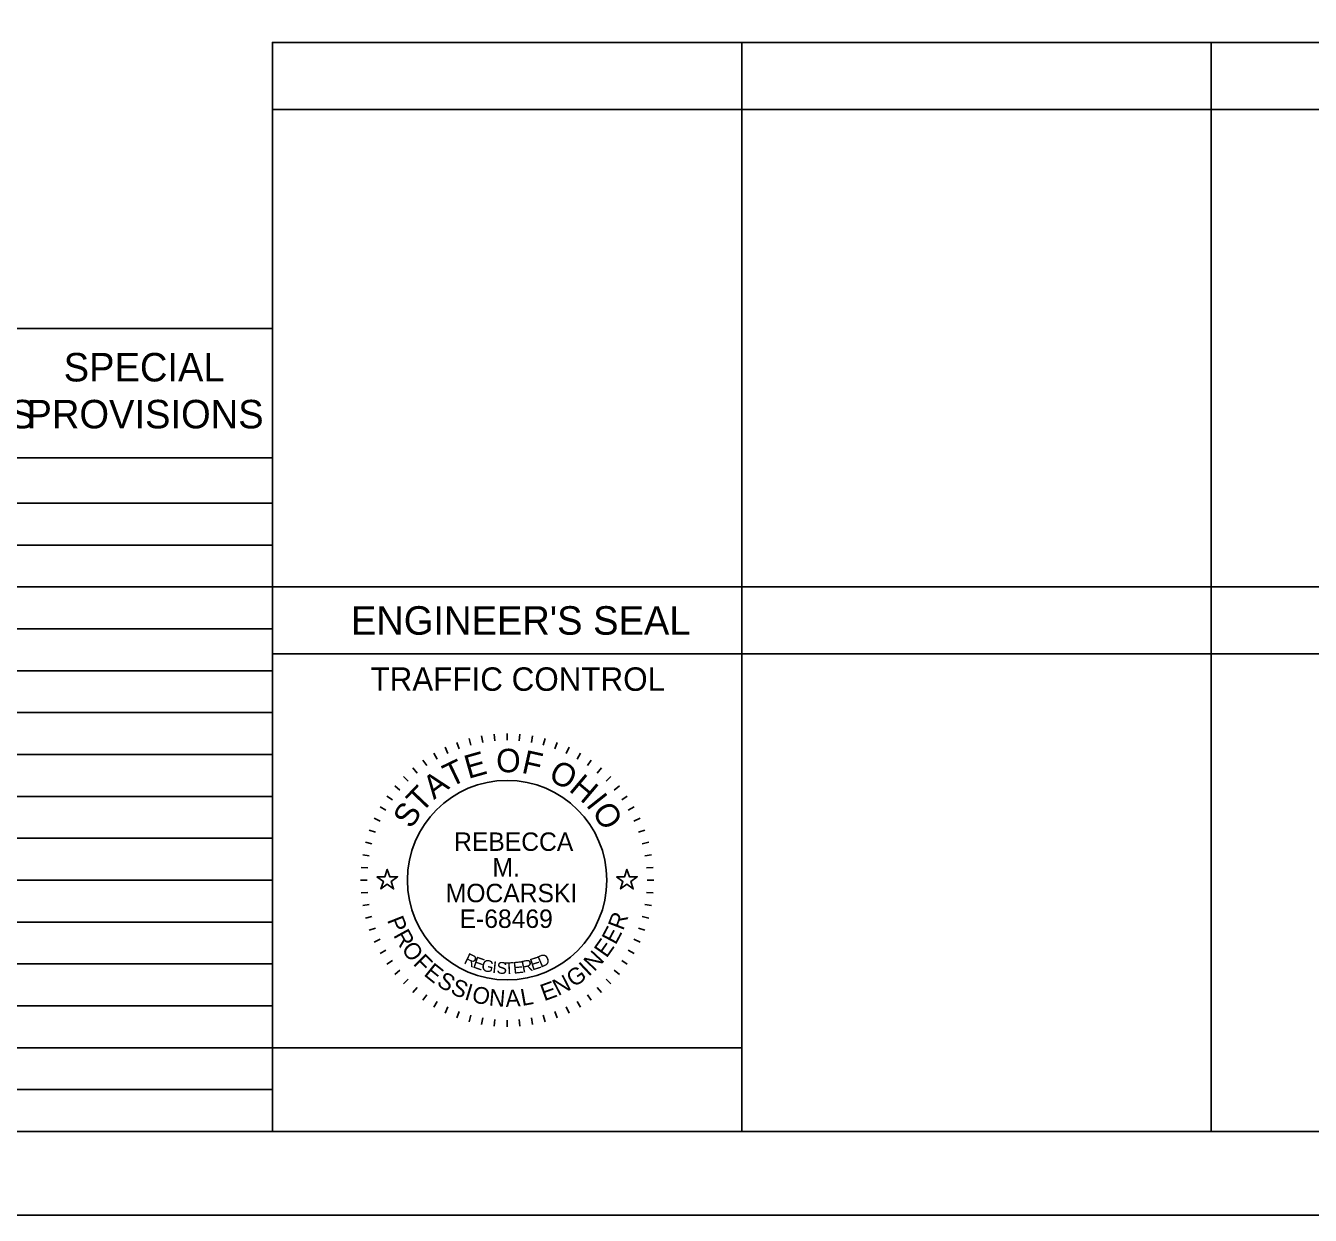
# Model space of a CAD drawing. Extents: x 0 to 29006, y 0 to 889393.
# Drawn here: x 22.13 to 29.79, y 0 to 7.1 of the extents above; entities that cross this region are included whole.
import ezdxf

# ---------------------------------------------------------------- set-up
doc = ezdxf.new("R2010")
doc.units = 0
for name, color, linetype in [('GM_X_Corporation', 7, 'Continuous'), ('SH_Border', 7, 'Continuous'), ('SH_Cut_Line', 7, 'Continuous'), ('SH_Data', 7, 'Continuous'), ('SH_Text', 7, 'Continuous')]:
    doc.layers.add(name, color=color, linetype=linetype)

msp = doc.modelspace()

# ---------------------------------------------------------------- linework, layer by layer
at = {"layer": 'GM_X_Corporation'}
for p, q in [((24.7735, 2.8452), (24.7839, 2.8065)), ((24.8481, 2.8617), (24.855, 2.8223)), ((24.9237, 2.8717), (24.9272, 2.8318)), ((25, 2.875), (25, 2.835)), ((25.0763, 2.8717), (25.0728, 2.8318)), ((25.1519, 2.8617), (25.145, 2.8223)), ((25.2265, 2.8452), (25.2161, 2.8065)), ((24.6302, 2.793), (24.6471, 2.7568)), ((24.7007, 2.8222), (24.7144, 2.7846)), ((25.2993, 2.8222), (25.2856, 2.7846)), ((25.3698, 2.793), (25.3529, 2.7568)), ((24.4981, 2.7168), (24.5211, 2.684)), ((24.5625, 2.7578), (24.5825, 2.7231)), ((25.4375, 2.7578), (25.4175, 2.7231)), ((25.5019, 2.7168), (25.4789, 2.684)), ((24.3813, 2.6187), (24.4096, 2.5904)), ((24.4376, 2.6703), (24.4633, 2.6396)), ((25.5624, 2.6703), (25.5367, 2.6396)), ((25.6187, 2.6187), (25.5904, 2.5904)), ((24.3297, 2.5624), (24.3604, 2.5367)), ((25.6703, 2.5624), (25.6396, 2.5367)), ((24.2832, 2.5019), (24.316, 2.4789)), ((25.7168, 2.5019), (25.684, 2.4789)), ((24.2422, 2.4375), (24.2769, 2.4175)), ((25.7578, 2.4375), (25.7231, 2.4175)), ((24.207, 2.3698), (24.2432, 2.3529)), ((25.793, 2.3698), (25.7568, 2.3529)), ((24.1548, 2.2265), (24.1935, 2.2161)), ((24.1778, 2.2993), (24.2154, 2.2856)), ((25.8222, 2.2993), (25.7846, 2.2856)), ((25.8452, 2.2265), (25.8065, 2.2161)), ((24.1383, 2.1519), (24.1777, 2.145)), ((25.8617, 2.1519), (25.8223, 2.145)), ((24.1283, 2.0763), (24.1682, 2.0728)), ((25.8717, 2.0763), (25.8318, 2.0728)), ((24.125, 2), (24.165, 2)), ((25.875, 2), (25.835, 2)), ((24.1283, 1.9237), (24.1682, 1.9272)), ((25.8717, 1.9237), (25.8318, 1.9272)), ((24.1383, 1.8481), (24.1777, 1.855)), ((25.8617, 1.8481), (25.8223, 1.855)), ((24.1548, 1.7735), (24.1935, 1.7839)), ((25.8452, 1.7735), (25.8065, 1.7839)), ((24.1778, 1.7007), (24.2154, 1.7144)), ((25.8222, 1.7007), (25.7846, 1.7144)), ((24.207, 1.6302), (24.2432, 1.6471)), ((25.793, 1.6302), (25.7568, 1.6471)), ((24.2422, 1.5625), (24.2769, 1.5825)), ((25.7578, 1.5625), (25.7231, 1.5825)), ((24.2832, 1.4981), (24.316, 1.5211)), ((24.3297, 1.4376), (24.3604, 1.4633)), ((25.6703, 1.4376), (25.6396, 1.4633)), ((25.7168, 1.4981), (25.684, 1.5211)), ((24.3813, 1.3813), (24.4096, 1.4096)), ((25.6187, 1.3813), (25.5904, 1.4096)), ((24.4376, 1.3297), (24.4633, 1.3604)), ((24.4981, 1.2832), (24.5211, 1.316)), ((25.5019, 1.2832), (25.4789, 1.316)), ((25.5624, 1.3297), (25.5367, 1.3604)), ((24.5625, 1.2422), (24.5825, 1.2769)), ((24.6302, 1.207), (24.6471, 1.2432)), ((25.3698, 1.207), (25.3529, 1.2432)), ((25.4375, 1.2422), (25.4175, 1.2769)), ((24.7007, 1.1778), (24.7144, 1.2154)), ((24.7735, 1.1548), (24.7839, 1.1935)), ((24.8481, 1.1383), (24.855, 1.1777)), ((24.9237, 1.1283), (24.9272, 1.1682)), ((25, 1.125), (25, 1.165)), ((25.0763, 1.1283), (25.0728, 1.1682)), ((25.1519, 1.1383), (25.145, 1.1777)), ((25.2265, 1.1548), (25.2161, 1.1935)), ((25.2993, 1.1778), (25.2856, 1.2154))]:
    msp.add_line(p, q, dxfattribs=at)
for points in [[(24.2236, 2.02), (24.2705, 2.02), (24.285, 2.0645), (24.2995, 2.02), (24.3464, 2.02), (24.3085, 1.9924), (24.323, 1.9478), (24.285, 1.9754), (24.247, 1.9478), (24.2615, 1.9924)], [(25.6536, 2.02), (25.7005, 2.02), (25.715, 2.0645), (25.7295, 2.02), (25.7764, 2.02), (25.7385, 1.9924), (25.753, 1.9478), (25.715, 1.9754), (25.677, 1.9478), (25.6915, 1.9924)]]:
    msp.add_lwpolyline(points, close=True, dxfattribs=at)
msp.add_circle((25, 2), 0.595, dxfattribs=at)
at = {"layer": 'SH_Border'}
msp.add_lwpolyline([(1.5, 21.5), (33.5, 21.5), (33.5, 0.5), (1.5, 0.5)], close=True, dxfattribs=at)
at = {"layer": 'SH_Cut_Line'}
msp.add_lwpolyline([(0, 0), (34, 0), (34, 22), (0, 22)], close=True, dxfattribs=at)
at = {"layer": 'SH_Data'}
for p, q in [((23.6, 6.6), (26.4, 6.6)), ((26.4, 6.6), (29.2, 6.6)), ((29.2, 6.6), (32, 6.6)), ((10.15, 5.2917), (23.6, 5.2917)), ((23.6, 0.5), (23.6, 5.2917)), ((10.15, 4.5209), (23.6, 4.5209)), ((10.15, 4.25), (23.6, 4.25)), ((10.15, 4), (23.6, 4)), ((10.15, 3.75), (23.6, 3.75)), ((23.6, 0.5), (23.6, 3.75)), ((23.6, 3.75), (26.4, 3.75)), ((26.4, 3.75), (26.4, 0.5)), ((10.15, 3.5), (23.6, 3.5)), ((23.6, 3.35), (26.4, 3.35)), ((23.6, 3.35), (26.4, 3.35)), ((26.4, 3.35), (29.2, 3.35)), ((29.2, 3.35), (32, 3.35)), ((10.15, 3.25), (23.6, 3.25)), ((10.15, 3), (23.6, 3)), ((10.15, 2.75), (23.6, 2.75)), ((10.15, 2.5), (23.6, 2.5)), ((10.15, 2.25), (23.6, 2.25)), ((10.15, 2), (23.6, 2)), ((10.15, 1.75), (23.6, 1.75)), ((10.15, 1.5), (23.6, 1.5)), ((10.15, 1.25), (23.6, 1.25)), ((10.15, 1), (23.6, 1)), ((10.15, 0.75), (23.6, 0.75)), ((23.6, 0.5), (26.4, 0.5))]:
    msp.add_line(p, q, dxfattribs=at)
for points in [[(26.4, 7), (23.6, 7), (23.6, 3.75), (26.4, 3.75)], [(29.2, 7), (26.4, 7), (26.4, 3.75), (29.2, 3.75)], [(32, 7), (29.2, 7), (29.2, 3.75), (32, 3.75)], [(26.4, 3.75), (23.6, 3.75), (23.6, 0.5), (26.4, 0.5)], [(29.2, 3.75), (26.4, 3.75), (26.4, 0.5), (29.2, 0.5)], [(32, 3.75), (29.2, 3.75), (29.2, 0.5), (32, 0.5)], [(23.6, 0.5), (23.6, 1), (26.4, 1), (26.4, 0.5)]]:
    msp.add_lwpolyline(points, close=True, dxfattribs=at)

# ---------------------------------------------------------------- texts
at = {"layer": 'GM_X_Corporation'}
for s, height, rotation, p in [('E', 0.14, 15.75706, (24.7684, 2.6038)), ('O', 0.14, 359.78119, (24.9347, 2.6443)), ('F', 0.14, 347.43619, (25.0811, 2.6417)), ('T', 0.14, 25.71674, (24.6616, 2.5518)), ('O', 0.14, 332.25863, (25.2398, 2.6015)), ('A', 0.14, 36.47472, (24.5634, 2.4781)), ('H', 0.14, 319.91363, (25.3632, 2.5361)), ('T', 0.14, 46.4344, (24.4883, 2.3964)), ('S', 0.14, 57.19238, (24.4281, 2.3014)), ('I', 0.14, 308.36695, (25.4665, 2.4483)), ('O', 0.14, 303.14906, (25.5021, 2.4089)), ('P', 0.1, 291.49398, (24.2823, 1.7621)), ('R', 0.1, 69.23216, (25.6919, 1.6954)), ('R', 0.1, 298.73106, (24.319, 1.6717)), ('E', 0.1, 61.99508, (25.6476, 1.6098)), ('O', 0.1, 306.46664, (24.3655, 1.5883)), ('E', 0.1, 54.75801, (25.5933, 1.5314)), ('F', 0.1, 314.7068, (24.4343, 1.4983)), ('R', 0.07, 334.48695, (24.7375, 1.5051)), ('E', 0.07, 341.03996, (24.7906, 1.4801)), ('E', 0.07, 17.68363, (25.1498, 1.4602)), ('D', 0.07, 23.30524, (25.201, 1.477)), ('N', 0.1, 47.02243, (25.5202, 1.4508)), ('E', 0.1, 321.43929, (24.4978, 1.4348)), ('G', 0.07, 347.47515, (24.8414, 1.4618)), ('I', 0.07, 353.78581, (24.9091, 1.4468)), ('S', 0.07, 356.89262, (24.9358, 1.4429)), ('T', 0.07, 3.00609, (24.9857, 1.4387)), ('E', 0.07, 6.01169, (25.0389, 1.4412)), ('R', 0.07, 11.91844, (25.0925, 1.4474)), ('G', 0.1, 35.04687, (25.3981, 1.357)), ('I', 0.1, 43.28703, (25.4868, 1.4214)), ('S', 0.1, 328.67637, (24.5743, 1.3752)), ('S', 0.1, 335.91345, (24.6564, 1.3266)), ('I', 0.1, 343.15053, (24.7406, 1.2897)), ('E', 0.1, 20.07421, (25.2212, 1.277)), ('N', 0.1, 27.31129, (25.3045, 1.3075)), ('O', 0.1, 346.88592, (24.7839, 1.2751)), ('N', 0.1, 355.12608, (24.8888, 1.2517)), ('A', 0.1, 2.86166, (24.9923, 1.2437)), ('L', 0.1, 10.09874, (25.0894, 1.249))]:
    msp.add_text(s, height=height, rotation=rotation, dxfattribs=at).set_placement(p)
for s, p in [('REBECCA', (24.6837, 2.1749)), ('M.', (24.9126, 2.0216)), ('MOCARSKI', (24.634, 1.8684)), ('E-68469', (24.7166, 1.7151))]:
    msp.add_text(s, height=0.11, dxfattribs=at).set_placement(p)
at = {"layer": 'SH_Data'}
for s, height, p in [("ENGINEER'S SEAL", 0.17, (24.0676, 3.465)), ('TRAFFIC CONTROL', 0.14, (24.1847, 3.13))]:
    msp.add_text(s, height=height, dxfattribs=at).set_placement(p)
at = {"layer": 'SH_Text'}
for s, p in [('SPECIAL', (22.3542, 4.9763)), ('SPECIFICATIONS', (20.2871, 4.6963)), ('PROVISIONS', (22.1323, 4.6963))]:
    msp.add_text(s, height=0.17, dxfattribs=at).set_placement(p)

doc.saveas('drawing.dxf')
